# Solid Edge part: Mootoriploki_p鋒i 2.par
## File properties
Author: KULL
Template: Iso Metric Part.par
Last saved by: KULL
Revision: 7
Application: Solid Edge
Accuracy: 0,990
Face Style: Model Default
Fill Style: Normal
Coef. of Thermal Exp: 0.0
Thermal Conductivity: 0.0
Specific Heat: 0.0
Modulus of Elasticity: 0.0
Poisson's Ratio: 0.0
Yield Stress: 0.0
Ultimate Stress: 0.0
Elongation: 0.0
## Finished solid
Body 1: solid body, 80 faces, 206 edges, 128 vertices.
  Faces by surface: plane 48, cylinder 22, torus 6, blend 4
  Edges by curve: line 136, circle 50, ellipse 20
Bounding box of the edges (mm; curved faces can reach further): 102.794 x 41.246 x 20.427, from (-51.3987, -20.6232, -4.4677) to (51.3957, 20.6232, 15.959).
Cylindrical faces by radius (mm): R3 x2, R4 x8, R6 x4, R8 x6, R9.5 x2
Toroidal faces (ring radius, tube radius in mm): R8.2 r0.2 x2, R9.3 r0.2 x2, R11.5 r2 x2
Planar faces by outward normal: +x 8, +z 17, -x 8, -z 1, oblique 14
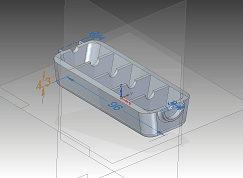
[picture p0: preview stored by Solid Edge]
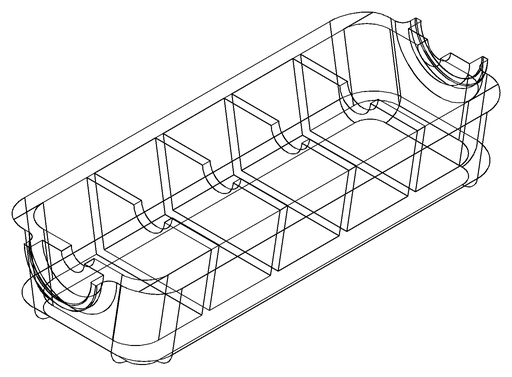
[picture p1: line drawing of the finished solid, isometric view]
